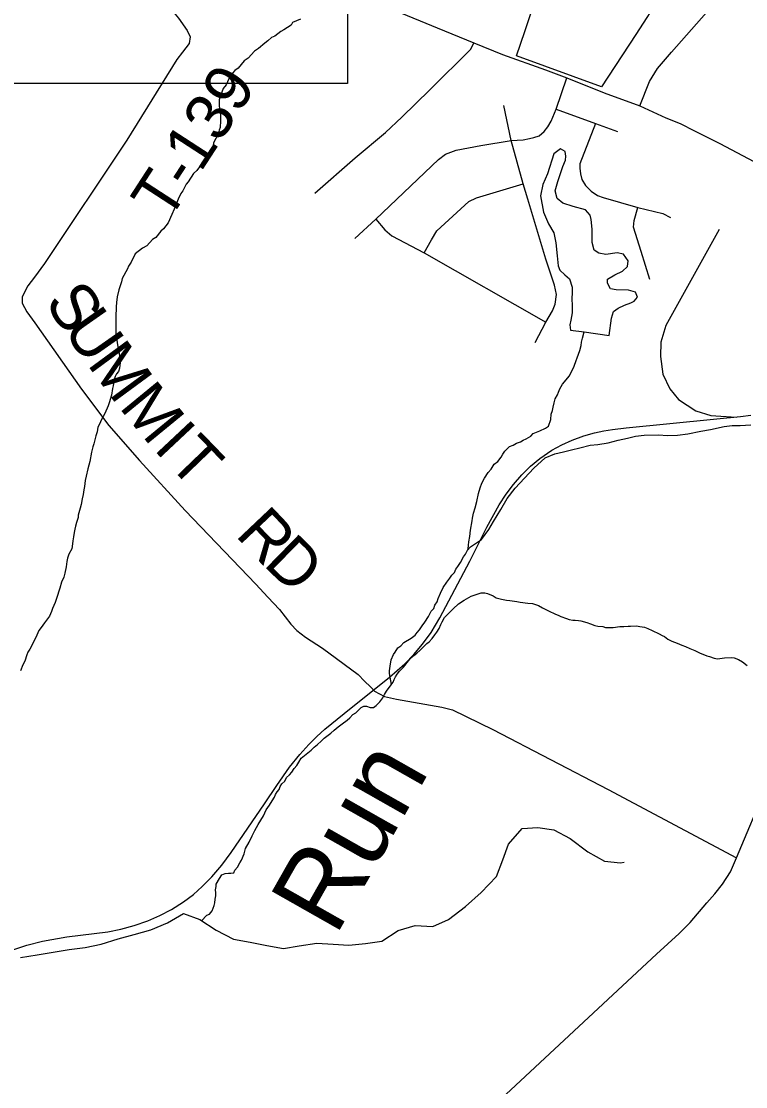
# Model space of a CAD drawing. Extents: x 0 to 34, y 0 to 22.
# Drawn here: x 7.407 to 8.286, y 15.409 to 16.702 of the extents above; entities that cross this region are included whole.
import ezdxf

# ---------------------------------------------------------------- set-up
doc = ezdxf.new("R2010")
doc.units = 0
for name, color, linetype in [('GM_X_Corporation', 7, 'Continuous'), ('GM_X_County_Road', 7, 'Continuous'), ('GM_X_Minor_Lake', 7, 'Continuous'), ('GM_X_Minor_River', 7, 'Continuous'), ('GM_X_Minor_River_Text', 7, 'Continuous'), ('GM_X_Rail_Line', 7, 'Continuous'), ('GM_X_Township_Road', 7, 'Continuous'), ('GM_X_Township_Road_Text', 7, 'Continuous'), ('SH_Masking', 7, 'Continuous'), ('SH_Text', 7, 'Continuous')]:
    doc.layers.add(name, color=color, linetype=linetype)

msp = doc.modelspace()

# ---------------------------------------------------------------- linework, layer by layer
at = {"layer": 'GM_X_Corporation'}
msp.add_lwpolyline([(8.1834, 16.7337), (8.1529, 16.6863), (8.1111, 16.6228), (8.0083, 16.6604), (8.0182, 16.6901), (8.0418, 16.7603)], dxfattribs=at)
at = {"layer": 'GM_X_County_Road'}
msp.add_lwpolyline([(7.6643, 16.8192), (7.7102, 16.793), (7.7437, 16.7732), (7.7803, 16.752), (7.8095, 16.7352), (7.8616, 16.7151), (7.9117, 16.6946), (7.9564, 16.6765), (7.9912, 16.6622), (8.0435, 16.6435), (8.0693, 16.6339), (8.1144, 16.6156), (8.158, 16.5998), (8.1895, 16.5855), (8.2066, 16.5786), (8.2241, 16.5696), (8.2549, 16.5543), (8.3032, 16.5286), (8.5388, 16.3863), (8.6502, 16.3199), (8.7056, 16.2911)], dxfattribs=at)
at = {"layer": 'GM_X_Minor_Lake'}
for points in [[(8.0902, 16.3257), (8.1206, 16.3211), (8.1236, 16.342), (8.1257, 16.3503), (8.1314, 16.3544), (8.1391, 16.358), (8.1468, 16.3609), (8.151, 16.3628), (8.1549, 16.3676), (8.1527, 16.3737), (8.144, 16.3762), (8.1291, 16.3764), (8.1223, 16.3777), (8.1186, 16.3846), (8.1187, 16.3895), (8.1276, 16.3947), (8.1368, 16.3991), (8.1429, 16.4047), (8.1438, 16.4119), (8.1379, 16.42), (8.1303, 16.4216), (8.1166, 16.4196), (8.1079, 16.4212), (8.1022, 16.4248), (8.1001, 16.4339), (8.1, 16.4502), (8.0987, 16.462), (8.0976, 16.467), (8.092, 16.4735), (8.0769, 16.4776), (8.0644, 16.4816), (8.0573, 16.4874), (8.0551, 16.4966), (8.0584, 16.5079), (8.0644, 16.5264), (8.0676, 16.534), (8.068, 16.5389), (8.067, 16.5446), (8.0617, 16.5478), (8.0536, 16.5418), (8.0456, 16.5173), (8.0401, 16.5045), (8.0372, 16.4908), (8.041, 16.471), (8.0469, 16.4565), (8.0535, 16.4457), (8.056, 16.4335), (8.0576, 16.4179), (8.0585, 16.4058), (8.0607, 16.4004), (8.0667, 16.3946), (8.0723, 16.3899)], [(8.0723, 16.3899), (8.0756, 16.3796), (8.0755, 16.3728), (8.0754, 16.366), (8.0756, 16.3572), (8.0758, 16.3485), (8.0742, 16.3398), (8.0729, 16.3341), (8.0736, 16.3276), (8.0902, 16.3257)]]:
    msp.add_lwpolyline(points, dxfattribs=at)
at = {"layer": 'GM_X_Minor_River'}
for points in [[(7.7461, 16.705), (7.7361, 16.7009), (7.7345, 16.6979), (7.7257, 16.692), (7.7219, 16.6902), (7.7149, 16.6846), (7.7107, 16.6828), (7.7065, 16.6787), (7.7026, 16.6761), (7.6949, 16.6694), (7.6903, 16.6664), (7.6825, 16.6578), (7.6775, 16.6545), (7.6702, 16.6455), (7.6663, 16.6429), (7.6605, 16.6361), (7.6558, 16.6252), (7.6523, 16.6211), (7.6491, 16.6131), (7.6471, 16.6071), (7.6473, 16.5995), (7.6487, 16.5907), (7.6489, 16.5816), (7.6484, 16.5736), (7.6472, 16.5702), (7.646, 16.5653), (7.6405, 16.5548), (7.6401, 16.5517), (7.6358, 16.5431), (7.6307, 16.5374)], [(7.6307, 16.5374), (7.6284, 16.5325), (7.6202, 16.5213), (7.6159, 16.5176), (7.6097, 16.5078), (7.607, 16.5048), (7.603, 16.4965), (7.6007, 16.4935), (7.5976, 16.4867), (7.594, 16.4773), (7.5928, 16.4743), (7.59, 16.4678), (7.5853, 16.458), (7.5795, 16.4505), (7.5764, 16.4476), (7.5702, 16.4401), (7.5663, 16.4375), (7.5593, 16.43), (7.5544, 16.427), (7.5455, 16.4204), (7.5404, 16.4102), (7.5373, 16.4053), (7.5361, 16.4019), (7.5294, 16.3902), (7.5286, 16.3861), (7.5254, 16.3766), (7.5233, 16.3679), (7.5228, 16.3611), (7.5224, 16.3558), (7.5218, 16.3432), (7.5217, 16.3379), (7.5218, 16.3231), (7.5225, 16.3178), (7.5242, 16.3075), (7.5249, 16.304), (7.527, 16.2911), (7.5269, 16.288), (7.5264, 16.2816), (7.5249, 16.2774), (7.5225, 16.2744), (7.5209, 16.2714), (7.5197, 16.2676), (7.5185, 16.2601), (7.5177, 16.2567), (7.5164, 16.2487), (7.5139, 16.2392), (7.5124, 16.2358), (7.5084, 16.2264), (7.5041, 16.2185), (7.5025, 16.2144), (7.5001, 16.2098), (7.4993, 16.2042), (7.4977, 16.1992), (7.4952, 16.1894), (7.494, 16.186), (7.4924, 16.1796), (7.4903, 16.1682), (7.4879, 16.1591), (7.4858, 16.1504), (7.4846, 16.1451), (7.4837, 16.1379), (7.4829, 16.1338), (7.4821, 16.1281), (7.4808, 16.1228), (7.4799, 16.1159), (7.4787, 16.1114), (7.4763, 16.1031), (7.4763, 16.1001), (7.4743, 16.094), (7.473, 16.0898), (7.4722, 16.0861), (7.4714, 16.0819), (7.4705, 16.0766), (7.4697, 16.0717), (7.4693, 16.0682), (7.4684, 16.0622), (7.4649, 16.0558), (7.4633, 16.0509), (7.4624, 16.0467), (7.4616, 16.0403), (7.4599, 16.0327), (7.4587, 16.0278), (7.4559, 16.0217), (7.4539, 16.0142), (7.4527, 16.0108), (7.4511, 16.0055), (7.4483, 15.9968), (7.4451, 15.9896), (7.4436, 15.9862), (7.4412, 15.9806), (7.4353, 15.9723), (7.4311, 15.9667), (7.4283, 15.9629), (7.426, 15.9573), (7.4216, 15.9482), (7.4173, 15.9403), (7.415, 15.9366), (7.4138, 15.9335), (7.4114, 15.9256), (7.409, 15.9215), (7.4062, 15.9139)], [(7.8565, 15.8975), (7.854, 15.911), (7.8541, 15.9141), (7.8546, 15.9197), (7.8562, 15.9273), (7.859, 15.9337), (7.8609, 15.9367), (7.8641, 15.942), (7.8679, 15.9446), (7.8714, 15.9483), (7.8802, 15.9539), (7.8852, 15.9572), (7.8876, 15.9606), (7.8903, 15.964), (7.8938, 15.9685), (7.8969, 15.9733), (7.9012, 15.9801), (7.9047, 15.9865), (7.9078, 15.9899), (7.909, 15.9937), (7.9118, 15.9978), (7.913, 16.0019), (7.9157, 16.0084), (7.9193, 16.0151), (7.9236, 16.0215), (7.9271, 16.0264), (7.9298, 16.0302), (7.9329, 16.0335), (7.9345, 16.0373), (7.9368, 16.0407), (7.9403, 16.0456), (7.9438, 16.0523), (7.9462, 16.0557), (7.9478, 16.0591), (7.9493, 16.0621), (7.9498, 16.0667), (7.9502, 16.0708), (7.9515, 16.0773), (7.9524, 16.0849), (7.9545, 16.0962), (7.9549, 16.0993), (7.9561, 16.1053), (7.9578, 16.1118), (7.9598, 16.1197), (7.9622, 16.1295), (7.9639, 16.136), (7.9659, 16.142), (7.9694, 16.148), (7.9737, 16.1548), (7.9772, 16.1589), (7.9811, 16.1649), (7.9853, 16.1683), (7.9896, 16.1735), (7.9916, 16.1769), (7.9939, 16.1807), (7.9997, 16.1863), (8.0039, 16.1881), (8.0081, 16.1903), (8.0131, 16.1921), (8.0162, 16.194), (8.02, 16.1958), (8.0254, 16.1987), (8.0285, 16.2021), (8.0365, 16.2054), (8.0434, 16.2087), (8.0469, 16.2109), (8.0497, 16.2192), (8.0502, 16.2257), (8.0518, 16.2302), (8.0526, 16.234), (8.0538, 16.2393), (8.055, 16.2442), (8.0578, 16.2491), (8.059, 16.2525), (8.0606, 16.2563), (8.0641, 16.2619), (8.0683, 16.2671), (8.0722, 16.2716), (8.0754, 16.2777), (8.0781, 16.2837), (8.0805, 16.2909), (8.0817, 16.2939), (8.0849, 16.303), (8.0865, 16.309), (8.087, 16.3128), (8.0882, 16.3177), (8.0902, 16.3257)], [(7.9483, 16.0601), (7.9524, 16.0646), (7.9655, 16.0735), (7.9744, 16.0855), (7.9803, 16.0953), (7.9893, 16.11), (7.9967, 16.1231), (8.0064, 16.1359), (8.0177, 16.1478), (8.0293, 16.1602), (8.0428, 16.1724), (8.0547, 16.1776), (8.065, 16.18), (8.0749, 16.1822), (8.0848, 16.1846), (8.0974, 16.1878), (8.107, 16.1888), (8.1192, 16.1909), (8.1314, 16.1941), (8.1428, 16.1965), (8.1524, 16.199), (8.163, 16.2), (8.1802, 16.2005), (8.1919, 16.1999), (8.2037, 16.2001), (8.2159, 16.2017), (8.2319, 16.2049), (8.2434, 16.207), (8.2602, 16.2105), (8.2697, 16.2118), (8.2796, 16.212), (8.2925, 16.2126)], [(7.6259, 15.6107), (7.6324, 15.6173), (7.6355, 15.6188), (7.6386, 15.6229), (7.6398, 15.6259), (7.641, 15.6293), (7.6418, 15.6323), (7.6422, 15.6369), (7.6431, 15.6411), (7.6431, 15.6445), (7.6428, 15.6483), (7.6436, 15.6521), (7.6437, 15.6551), (7.6476, 15.6619), (7.6503, 15.6664), (7.6546, 15.6682), (7.6584, 15.6685), (7.6614, 15.6685), (7.6652, 15.6688), (7.6664, 15.6722), (7.6695, 15.6756), (7.6723, 15.6812), (7.6742, 15.6842), (7.6774, 15.6918), (7.6794, 15.6986), (7.6837, 15.7061), (7.6872, 15.7136), (7.6904, 15.7204), (7.6947, 15.7276), (7.6978, 15.7328), (7.701, 15.7381), (7.7041, 15.7453), (7.7084, 15.7509), (7.7115, 15.7562), (7.7143, 15.7607), (7.7158, 15.7641), (7.7178, 15.7671), (7.7201, 15.7701), (7.7213, 15.7735), (7.7233, 15.7769), (7.7268, 15.7802), (7.7291, 15.7844), (7.7326, 15.7877), (7.7353, 15.7911), (7.7384, 15.7956), (7.7415, 15.7993), (7.7439, 15.8031), (7.7466, 15.808), (7.7589, 15.8177), (7.7624, 15.8214), (7.7667, 15.8248), (7.7709, 15.8285), (7.7748, 15.8322), (7.7829, 15.8382), (7.7867, 15.8419), (7.7917, 15.846), (7.7964, 15.8497), (7.8025, 15.8541), (7.806, 15.8571), (7.8095, 15.8609), (7.8133, 15.8631), (7.8164, 15.8664), (7.8195, 15.8694), (7.823, 15.8713), (7.826, 15.8712), (7.8305, 15.8696), (7.8347, 15.8695), (7.8378, 15.8718), (7.8424, 15.8763), (7.8459, 15.8811), (7.8479, 15.8853), (7.8502, 15.8894), (7.8561, 15.8969), (7.8584, 15.9003), (7.8596, 15.9037), (7.8612, 15.9067), (7.8631, 15.9101), (7.8662, 15.9138), (7.8709, 15.9187), (7.8787, 15.9281), (7.8837, 15.9325), (7.8871, 15.9355), (7.8914, 15.9392), (7.8952, 15.943), (7.8991, 15.9471), (7.9022, 15.9493), (7.9057, 15.9534), (7.9092, 15.9579), (7.9115, 15.9609), (7.9143, 15.9654), (7.9162, 15.9703), (7.9178, 15.9737), (7.9209, 15.9786), (7.9236, 15.9816), (7.9314, 15.9895), (7.9376, 15.9954), (7.9445, 15.9999), (7.9533, 16.0047), (7.9579, 16.0065), (7.9652, 16.0086), (7.9697, 16.0086)], [(7.9697, 16.0086), (7.9728, 16.0081), (7.9799, 16.005), (7.9833, 16.0026), (7.9901, 16.001), (7.9958, 15.9997), (8, 15.9993), (8.0087, 15.9984), (8.0125, 15.9975), (8.022, 15.9962), (8.0277, 15.9958), (8.0349, 15.9934), (8.0398, 15.9906), (8.0469, 15.9867), (8.0556, 15.9827), (8.0586, 15.9815), (8.062, 15.98), (8.0688, 15.9776), (8.0722, 15.9764), (8.0764, 15.9755), (8.0794, 15.9755), (8.0832, 15.975), (8.0862, 15.9746), (8.0934, 15.9729), (8.098, 15.9713), (8.1033, 15.969), (8.1067, 15.9682), (8.1131, 15.9677), (8.1162, 15.9668), (8.1253, 15.9667), (8.1337, 15.9677), (8.1382, 15.968), (8.1435, 15.9683), (8.1466, 15.9682), (8.1538, 15.9685), (8.158, 15.968), (8.1633, 15.9672), (8.1675, 15.9656), (8.1727, 15.9632), (8.1814, 15.9589), (8.1848, 15.9569), (8.1878, 15.9557), (8.1916, 15.9526), (8.1965, 15.9502), (8.2033, 15.9478), (8.2089, 15.9451), (8.2131, 15.9435), (8.2184, 15.9411), (8.2244, 15.9387), (8.2312, 15.9356), (8.2342, 15.9344), (8.2391, 15.9324), (8.2422, 15.9316), (8.2482, 15.9296), (8.252, 15.9287), (8.255, 15.9291), (8.2604, 15.9297), (8.2688, 15.9304), (8.2725, 15.9299), (8.2775, 15.9279), (8.2823, 15.9248), (8.288, 15.9205)], [(7.5439, 15.5942), (7.5644, 15.5996), (7.5846, 15.6083), (7.6039, 15.6197), (7.6237, 15.6121), (7.6438, 15.5992), (7.6647, 15.5885), (7.6848, 15.5847), (7.7053, 15.5806), (7.7255, 15.5772), (7.7444, 15.5802), (7.7657, 15.5836), (7.7855, 15.5821), (7.8048, 15.581), (7.8249, 15.5832), (7.8447, 15.5859), (7.8644, 15.5988), (7.8853, 15.6049), (7.9066, 15.6037), (7.9256, 15.6121), (7.9461, 15.6281), (7.9654, 15.6451), (7.9837, 15.6645), (7.9916, 15.6846), (7.9985, 15.7036), (8.0148, 15.7226), (8.0342, 15.7238), (8.0535, 15.7211), (8.0733, 15.7105), (8.0945, 15.6945), (8.1151, 15.6831), (8.1344, 15.6812), (8.1386, 15.682)], [(7.4061, 15.5661), (7.4262, 15.5695), (7.4456, 15.5726), (7.4653, 15.576), (7.4847, 15.5783), (7.5041, 15.5821), (7.5246, 15.5889), (7.5439, 15.5942)]]:
    msp.add_lwpolyline(points, dxfattribs=at)
at = {"layer": 'GM_X_Rail_Line'}
for points in [[(8.254, 16.4496), (8.1893, 16.3333), (8.1831, 16.3131), (8.1828, 16.2956), (8.1856, 16.2742), (8.1943, 16.2562), (8.2049, 16.2433), (8.2257, 16.2295), (8.2439, 16.2241), (8.2747, 16.2221)], [(7.3968, 15.5754), (7.4138, 15.5811), (7.4328, 15.5861), (7.4623, 15.591), (7.5122, 15.5973), (7.528, 15.6003), (7.5442, 15.6049), (7.5608, 15.6105), (7.5754, 15.6172), (7.5893, 15.6243), (7.6039, 15.6338), (7.6159, 15.6427), (7.6268, 15.6524), (7.6385, 15.664), (7.6504, 15.678), (7.6617, 15.6935), (7.7022, 15.7526), (7.7173, 15.7748), (7.7328, 15.797), (7.7453, 15.8125), (7.7559, 15.8245), (7.7656, 15.8345), (7.7755, 15.8432), (7.7989, 15.8623), (7.8541, 15.9063), (7.8727, 15.9225), (7.8836, 15.9337), (7.894, 15.9464), (7.9044, 15.9607), (7.9149, 15.9782), (7.9513, 16.0473), (7.9722, 16.0886), (7.9871, 16.1157), (7.9956, 16.1284), (8.0045, 16.1403), (8.0145, 16.1519), (8.0253, 16.1623), (8.0364, 16.1716), (8.051, 16.1818), (8.0631, 16.1883), (8.0756, 16.194), (8.0899, 16.1995), (8.1026, 16.2028), (8.114, 16.2052), (8.1248, 16.2069), (8.1414, 16.209), (8.2472, 16.2195), (8.2799, 16.2226), (8.2925, 16.2243)]]:
    msp.add_lwpolyline(points, dxfattribs=at)
at = {"layer": 'GM_X_Township_Road'}
for points in [[(7.6643, 16.8192), (7.5864, 16.7331), (7.5849, 16.7255), (7.5873, 16.7198), (7.5919, 16.7135), (7.5979, 16.7061), (7.6086, 16.6913), (7.6121, 16.6835), (7.611, 16.6755), (7.6026, 16.6651), (7.5959, 16.6562), (7.535, 16.5582), (7.4354, 16.4084), (7.4233, 16.3921)], [(8.158, 16.5998), (8.1694, 16.6293), (8.1794, 16.6453), (8.1964, 16.6649), (8.2632, 16.741)], [(7.7633, 16.494), (7.8122, 16.5367), (7.8493, 16.5673), (7.8691, 16.5861), (7.9029, 16.6194), (7.9528, 16.6685), (7.9564, 16.6765)], [(7.8118, 16.439), (7.8372, 16.4621), (7.9133, 16.5347), (7.9221, 16.5412), (7.935, 16.546), (7.9649, 16.5517), (8.0017, 16.5579), (8.0161, 16.5585), (8.024, 16.5602), (8.0291, 16.5613), (8.0356, 16.5635), (8.0416, 16.5687), (8.0462, 16.5743), (8.05, 16.5811), (8.0564, 16.5958), (8.0693, 16.6339)], [(8.0306, 16.3127), (8.0437, 16.3373), (8.052, 16.351), (8.0552, 16.3592), (8.0565, 16.3708), (8.0544, 16.3823), (8.0439, 16.4138), (8.0218, 16.4866), (8.0162, 16.5052), (8.0017, 16.5579), (7.9928, 16.6002)], [(8.0564, 16.5958), (8.1042, 16.5783), (8.1308, 16.5686)], [(8.1042, 16.5783), (8.0849, 16.5296), (8.0849, 16.5243), (8.0856, 16.5175), (8.0874, 16.5104), (8.0918, 16.5033), (8.0989, 16.4962), (8.1066, 16.4909), (8.1134, 16.4887), (8.1555, 16.4764), (8.1859, 16.4693), (8.1952, 16.4643)], [(7.8959, 16.4214), (7.9048, 16.4373), (7.9116, 16.4482), (7.9504, 16.4838), (7.9597, 16.4882), (8.0162, 16.5052)], [(8.1701, 16.389), (8.1596, 16.4231), (8.15, 16.4525), (8.1509, 16.4606), (8.1555, 16.4764)], [(7.8372, 16.4621), (7.8483, 16.4493), (7.8569, 16.4419), (7.8959, 16.4214), (8.0437, 16.3373)], [(7.4233, 16.3921), (7.4152, 16.3812), (7.408, 16.3682), (7.4081, 16.3603), (7.4138, 16.3498), (7.4237, 16.3365), (7.4802, 16.2559), (7.5132, 16.2117), (7.5506, 16.1695), (7.6061, 16.1088), (7.6917, 16.0193), (7.7063, 16.0034), (7.7204, 15.9885), (7.7343, 15.9706), (7.7415, 15.9631), (7.7522, 15.9551), (7.7725, 15.9414), (7.816, 15.9097), (7.8235, 15.9017), (7.831, 15.8948), (7.8316, 15.894)], [(8.2752, 15.6869), (8.3119, 15.7744), (8.3541, 15.8765), (8.3826, 15.9455), (8.4411, 16.0875), (8.4579, 16.1277), (8.5195, 16.2798), (8.5413, 16.3373), (8.5477, 16.3553), (8.5529, 16.3615), (8.5597, 16.3617), (8.567, 16.3587), (8.605, 16.3364), (8.6285, 16.3211), (8.6401, 16.3142), (8.6475, 16.3144), (8.6502, 16.3199)], [(7.8316, 15.894), (7.8358, 15.8894), (7.848, 15.8828), (7.8625, 15.8796), (7.9174, 15.8701), (7.9304, 15.8666), (7.9796, 15.8427), (8.1192, 15.7701), (8.2752, 15.6869)], [(7.4124, 15.0048), (7.5436, 15.0417), (7.5533, 15.0445), (7.5615, 15.05), (7.7278, 15.156), (7.7386, 15.1623), (7.7463, 15.1686), (7.7654, 15.1857), (8.1779, 15.57), (8.2055, 15.5951), (8.2191, 15.6084), (8.2391, 15.6325), (8.2489, 15.6435), (8.2583, 15.655), (8.2679, 15.6699), (8.2752, 15.6869)]]:
    msp.add_lwpolyline(points, dxfattribs=at)
at = {"layer": 'SH_Masking'}
msp.add_lwpolyline([(7.8032, 16.6268), (5.8452, 16.6268), (5.8452, 17.1866), (7.8032, 17.1866)], close=True, dxfattribs=at)
at = {"layer": 'SH_Text'}
msp.add_lwpolyline([(7.8032, 16.6268), (5.8452, 16.6268), (5.8452, 17.1866), (7.8032, 17.1866)], close=True, dxfattribs=at)

# ---------------------------------------------------------------- texts
at = {"layer": 'GM_X_Minor_River_Text'}
msp.add_text('Run', height=0.09465, rotation=60.4503, dxfattribs=at).set_placement((7.7885, 15.5906))
at = {"layer": 'GM_X_Township_Road_Text'}
for s, height, rotation, p in [('T-139', 0.05682, 57.0111, (7.5855, 16.4579)), ('S', 0.0568, 303.8904, (7.4345, 16.3614)), ('U', 0.0568, 305.0466, (7.4566, 16.3285)), ('M', 0.0568, 306.3285, (7.4862, 16.2865)), ('M', 0.0568, 309.3609, (7.5247, 16.2342)), ('I', 0.0568, 313.1829, (7.5665, 16.1834)), ('T', 0.0568, 313.9402, (7.5831, 16.1658)), ('R', 0.0568, 313.4405, (7.6657, 16.0786)), ('D', 0.0568, 315.7509, (7.6996, 16.043))]:
    msp.add_text(s, height=height, rotation=rotation, dxfattribs=at).set_placement(p)

doc.saveas('drawing.dxf')
